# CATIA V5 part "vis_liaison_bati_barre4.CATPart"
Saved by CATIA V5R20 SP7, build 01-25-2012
Part number: skl_vis_liaison_bati_barre4
Bounding box of the stored display mesh (mm): x -7 to 20, y 0 to 0, z 0 to 0
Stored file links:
  J:\IFMA\IAO\système avant mef\vis_liaison_bati_barre4.CATPart
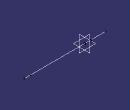
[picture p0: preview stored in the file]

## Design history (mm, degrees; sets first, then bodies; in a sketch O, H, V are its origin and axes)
Body1 (main body)
  Point1 "Point.F": stored without definition
  Point2 "Point.Fprim": stored without definition
  Point3 "Point_F_vis": stored without definition
  Point4 "Point.F": stored without definition
  Line1: type PtPt, FirstPoint Point3, SecondPoint Point4
  Plane1: stored without definition
  Point5 "Point.Fprim": stored without definition
  Line2 "axe_liaison_bati_barre4": type Normal, RefPoint Point5, RefSkin Plane1, Start 0, End 20
  Plane2 "Plan_ref": stored without definition
  Point6 "Point.F": stored without definition
  Line3 "axe_liaison_barre4_bati": type Normal, RefPoint Point6, RefSkin Plane2, Start 0, End 20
